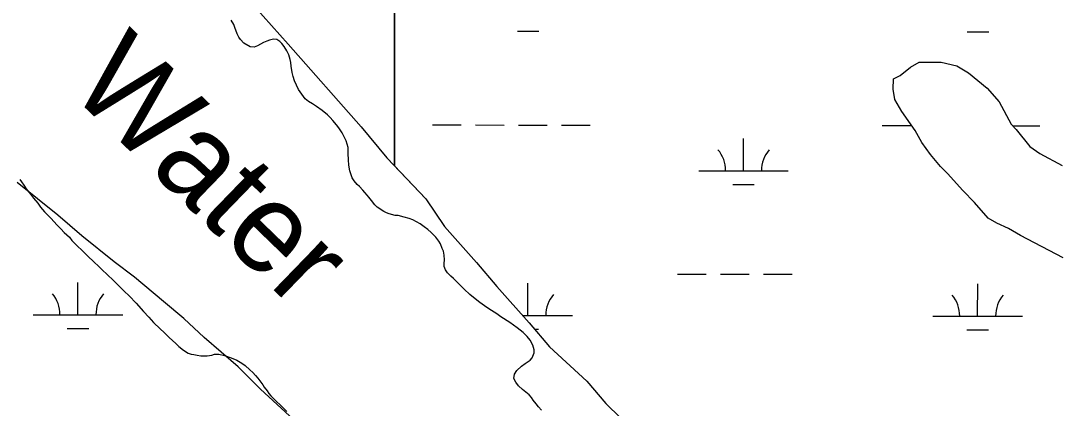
# Model space of a CAD drawing. Extents: x 3208593 to 3246461, y 812903 to 838290.
# Drawn here: x 3214585 to 3215741, y 820297 to 820730 of the extents above; entities that cross this region are included whole.
import ezdxf

# ---------------------------------------------------------------- set-up
doc = ezdxf.new("R2010")
doc.units = 0
for name, color, linetype in [('V-RIVR-IDEN', 7, 'Continuous'), ('V-SITE-VEGE', 7, 'Continuous'), ('V-TOPO-SHOR', 7, 'Continuous'), ('V-WETL-SWMP', 7, 'Continuous')]:
    doc.layers.add(name, color=color, linetype=linetype)

msp = doc.modelspace()

# ---------------------------------------------------------------- linework, layer by layer
at = {"layer": 'V-SITE-VEGE'}
for p, q in [((3214830.6, 820762.9), (3214883.7, 820703.4)), ((3214883.7, 820703.4), (3214965.1, 820611.3)), ((3215566.4, 820668.3), (3215577.9, 820677.8)), ((3215577.9, 820677.8), (3215587.5, 820683.4)), ((3215587.5, 820683.4), (3215612.3, 820683.3)), ((3215612.3, 820683.3), (3215629.5, 820679.4)), ((3215629.5, 820679.4), (3215642.8, 820671.6)), ((3215558.7, 820653.1), (3215558.8, 820664.6)), ((3215558.8, 820664.6), (3215566.4, 820668.3)), ((3215642.8, 820671.6), (3215663.6, 820654.3)), ((3215560.5, 820641.7), (3215558.7, 820653.1)), ((3215663.6, 820654.3), (3215676.9, 820639)), ((3215568.1, 820628.2), (3215560.5, 820641.7)), ((3215676.9, 820639), (3215690.1, 820614.1)), ((3215583.2, 820607.2), (3215568.1, 820628.2)), ((3214965.1, 820611.3), (3214993.5, 820576.7)), ((3215590.7, 820593.8), (3215583.2, 820607.2)), ((3215690.1, 820614.1), (3215695.8, 820608.3)), ((3215695.8, 820608.3), (3215710.9, 820589.1)), ((3215600.2, 820580.3), (3215590.7, 820593.8)), ((3215710.9, 820589.1), (3215722.3, 820581.4)), ((3214993.5, 820576.7), (3215037, 820530.7)), ((3215611.5, 820566.9), (3215600.2, 820580.3)), ((3215722.3, 820581.4), (3215747, 820567.9)), ((3215619.1, 820559.2), (3215611.5, 820566.9)), ((3214626.7, 820512.4), (3214581.2, 820549)), ((3215636.2, 820540), (3215619.1, 820559.2)), ((3215649.4, 820526.6), (3215636.2, 820540)), ((3215037, 820530.7), (3215057.8, 820500)), ((3215664.6, 820509.3), (3215649.4, 820526.6)), ((3214653.3, 820489.3), (3214626.7, 820512.4)), ((3215674.1, 820503.5), (3215664.6, 820509.3)), ((3215687.4, 820497.7), (3215674.1, 820503.5)), ((3215057.8, 820500), (3215093.8, 820459.7)), ((3215700.7, 820490), (3215687.4, 820497.7)), ((3214689.4, 820460.5), (3214653.3, 820489.3)), ((3215748.2, 820464.9), (3215700.7, 820490)), ((3214712.1, 820443.2), (3214689.4, 820460.5)), ((3215093.8, 820459.7), (3215116.5, 820432.8)), ((3214744.4, 820416.2), (3214712.1, 820443.2)), ((3215116.5, 820432.8), (3215152.5, 820392.5)), ((3214767.1, 820397), (3214744.4, 820416.2)), ((3214789.9, 820375.9), (3214767.1, 820397)), ((3215152.5, 820392.5), (3215175.2, 820365.7)), ((3214827.8, 820343.2), (3214789.9, 820375.9)), ((3215175.2, 820365.7), (3215216.9, 820327.2)), ((3214852.5, 820318.2), (3214827.8, 820343.2)), ((3214894.2, 820279.8), (3214852.5, 820318.2)), ((3215216.9, 820327.2), (3215237.8, 820302.3)), ((3215237.8, 820302.3), (3215277.6, 820263.9))]:
    msp.add_line(p, q, dxfattribs=at)
at = {"layer": 'V-TOPO-SHOR'}
for points in [[(3214937.6, 820613.5), (3214933.5, 820618.2), (3214930.3, 820621.5), (3214927.4, 820624.7), (3214921.6, 820629.4), (3214915.3, 820633.9), (3214910.6, 820636.7), (3214906.1, 820639.4), (3214902.5, 820642.4), (3214895, 820652.8), (3214890.7, 820662.5), (3214889.1, 820667.2), (3214887.9, 820671.9), (3214886.9, 820679), (3214886.5, 820683.1), (3214885.7, 820686.5), (3214884.2, 820691.4), (3214882, 820695.9), (3214879, 820700.9), (3214876.3, 820704.2), (3214874.1, 820706.6), (3214870.8, 820708.7), (3214867.2, 820709.1), (3214862.7, 820707.9), (3214859.7, 820706.9), (3214856, 820705.4), (3214852.5, 820703.6), (3214849.3, 820701.6), (3214845.4, 820700), (3214841, 820700.6), (3214833.9, 820704.4), (3214830.2, 820708.7), (3214828.6, 820711.3), (3214826.6, 820715), (3214823.9, 820722.1), (3214822.9, 820725.6), (3214820.1, 820730.1)], [(3215166.1, 820294.9), (3215162.9, 820298.4), (3215160.2, 820301.8), (3215156.8, 820306.1), (3215154.9, 820308.8), (3215152.5, 820311.8), (3215145, 820317.9), (3215140.7, 820321.8), (3215137.7, 820326), (3215135.5, 820330.3), (3215135.9, 820335), (3215138.7, 820339), (3215144, 820343.9), (3215147.9, 820346.8), (3215153.4, 820350.8), (3215155.6, 820353.4), (3215158, 820358.7), (3215158, 820362), (3215156.6, 820367.3), (3215153.4, 820373), (3215150.1, 820377), (3215145.7, 820381.5), (3215139, 820386.8), (3215130.8, 820392.7), (3215120.9, 820399), (3215116.2, 820402.3), (3215110.3, 820406.1), (3215105.2, 820409.6), (3215097.5, 820415.1), (3215092.1, 820419.3), (3215086.2, 820424), (3215079.9, 820429.9), (3215076.2, 820433.6), (3215072.8, 820436.8), (3215068.1, 820441.7), (3215065.1, 820444.4), (3215061.2, 820448.2), (3215059.2, 820451.5), (3215057.7, 820455.1), (3215057.7, 820458.6), (3215057.8, 820462.8), (3215057.5, 820467.7), (3215056.7, 820472.2), (3215055.5, 820475.3), (3215053.5, 820480.7), (3215051.5, 820483.6), (3215048.4, 820487.8), (3215043.2, 820493.3), (3215039.3, 820496.6), (3215035.4, 820499.6), (3215030.8, 820502.9), (3215022.6, 820507.2), (3215018.4, 820508.8), (3215012.9, 820510.4), (3215006.2, 820512.1), (3215003.1, 820512.3), (3214996.4, 820513.9), (3214993.4, 820515.3), (3214990.3, 820516.8), (3214983, 820521.4), (3214980.4, 820523.9), (3214976.5, 820529), (3214973.7, 820532.6), (3214971.5, 820534.9), (3214969.2, 820537.7), (3214966.8, 820540.3), (3214963.1, 820544.6), (3214960.5, 820546.7), (3214957, 820550.9), (3214955, 820554.4), (3214952.4, 820562.1), (3214951.4, 820568.4), (3214950.8, 820574.3), (3214950.6, 820581.4), (3214950.6, 820584.9), (3214950.4, 820588.1), (3214948.2, 820595.6), (3214943.9, 820604.4), (3214940.2, 820609.9), (3214937.6, 820613.5)], [(3214584, 820552.3), (3214585.8, 820549.6), (3214588.5, 820546), (3214591.3, 820542.1), (3214596.2, 820535.8), (3214599.4, 820531.5), (3214604.1, 820525.8), (3214607.1, 820521.6), (3214611.8, 820516.3), (3214615.1, 820513), (3214619.1, 820508.8), (3214625.4, 820501.8), (3214629.7, 820497.4), (3214633.7, 820493.3), (3214639.4, 820487.8), (3214642.3, 820484.4), (3214646.7, 820479.9), (3214655, 820471.7), (3214659.7, 820467.1), (3214667, 820460), (3214671.9, 820455.7), (3214675.1, 820452.4), (3214682.2, 820445.7), (3214687.7, 820440.4), (3214693.6, 820434.9), (3214700.7, 820427.6), (3214706.2, 820422.5), (3214713.9, 820414.2), (3214722.2, 820404.8), (3214727.9, 820398.7), (3214733.4, 820392.8), (3214740.7, 820385.5), (3214745, 820381.5), (3214750.7, 820375.8), (3214754.5, 820372.5), (3214758, 820369.2), (3214761.6, 820365.8), (3214766.7, 820361.7), (3214771.8, 820358.3), (3214775.2, 820357.5), (3214778.3, 820357), (3214782.1, 820356.2), (3214786.2, 820355.4), (3214789.5, 820355.4), (3214793.3, 820355.6), (3214798.2, 820356.4), (3214801.2, 820357.2), (3214806.1, 820357.2), (3214812.4, 820356), (3214820.1, 820353.3), (3214826.2, 820350.7), (3214831.9, 820347.2), (3214835.6, 820344.6), (3214840.8, 820339.9), (3214844.1, 820336.7), (3214847.1, 820333.6), (3214849.6, 820330.4), (3214853, 820326.1), (3214855.1, 820323), (3214856.9, 820320.4), (3214860.1, 820316.3), (3214862, 820313.3), (3214864, 820311), (3214866.6, 820308.4), (3214870.9, 820304.3), (3214874.3, 820301.1), (3214882.2, 820293.3)]]:
    msp.add_lwpolyline(points, dxfattribs=at)
at = {"layer": 'V-WETL-SWMP'}
for p, q in [((3215002, 821050.7), (3215002, 820567.7)), ((3215002, 820567.7), (3215002, 821050.7)), ((3214830.6, 820762.9), (3214883.7, 820703.4)), ((3215139.4, 820717.9), (3215163.4, 820717.8)), ((3215641.3, 820717.1), (3215665.3, 820717.1)), ((3214883.7, 820703.4), (3214965.1, 820611.3)), ((3215566.4, 820668.3), (3215577.9, 820677.8)), ((3215577.9, 820677.8), (3215587.5, 820683.4)), ((3215587.5, 820683.4), (3215612.3, 820683.3)), ((3215612.3, 820683.3), (3215629.5, 820679.4)), ((3215629.5, 820679.4), (3215642.8, 820671.6)), ((3215558.7, 820653.1), (3215558.8, 820664.6)), ((3215558.8, 820664.6), (3215566.4, 820668.3)), ((3215642.8, 820671.6), (3215663.6, 820654.3)), ((3215560.5, 820641.7), (3215558.7, 820653.1)), ((3215663.6, 820654.3), (3215676.9, 820639)), ((3215568.1, 820628.3), (3215560.5, 820641.7)), ((3215676.9, 820639), (3215690.1, 820614.1)), ((3215583.2, 820607.2), (3215568.1, 820628.3)), ((3214965.1, 820611.3), (3214993.5, 820576.7)), ((3215044.4, 820613.4), (3215076.4, 820613.3)), ((3215092.4, 820613.3), (3215124.4, 820613.2)), ((3215140.4, 820613.2), (3215172.4, 820613.2)), ((3215188.4, 820613.1), (3215220.4, 820613.1)), ((3215546.3, 820612.6), (3215578.3, 820612.6)), ((3215590.7, 820593.8), (3215583.2, 820607.2)), ((3215690.1, 820614.1), (3215695.8, 820608.3)), ((3215691.7, 820612.4), (3215722.3, 820612.4)), ((3215695.8, 820608.3), (3215710.9, 820589.1)), ((3215391.6, 820562.1), (3215391.7, 820598.1)), ((3215600.2, 820580.3), (3215590.7, 820593.8)), ((3215710.9, 820589.1), (3215722.3, 820581.4)), ((3214993.5, 820576.7), (3215002, 820567.7)), ((3215611.5, 820566.9), (3215600.2, 820580.3)), ((3215722.3, 820581.4), (3215747, 820567.9)), ((3215002, 820567.7), (3215037.1, 820530.7)), ((3215341.6, 820562.2), (3215441.6, 820562)), ((3215619.1, 820559.2), (3215611.5, 820566.9)), ((3214626.7, 820512.4), (3214581.2, 820549)), ((3215636.2, 820540), (3215619.1, 820559.2)), ((3215379.6, 820546.7), (3215403.6, 820546.7)), ((3215649.4, 820526.6), (3215636.2, 820540)), ((3215037.1, 820530.7), (3215057.8, 820500)), ((3215664.6, 820509.3), (3215649.4, 820526.6)), ((3214653.3, 820489.3), (3214626.7, 820512.4)), ((3215674.1, 820503.5), (3215664.6, 820509.3)), ((3215687.4, 820497.7), (3215674.1, 820503.5)), ((3215057.8, 820500), (3215093.8, 820459.7)), ((3215700.7, 820490), (3215687.4, 820497.7)), ((3214689.4, 820460.5), (3214653.3, 820489.3)), ((3215748.2, 820464.9), (3215700.7, 820490)), ((3214712.1, 820443.2), (3214689.4, 820460.5)), ((3215093.8, 820459.7), (3215116.5, 820432.8)), ((3215318, 820446.8), (3215350, 820446.7)), ((3215366, 820446.7), (3215398, 820446.7)), ((3215414, 820446.6), (3215446, 820446.6)), ((3214649, 820401.3), (3214649, 820437.3)), ((3214744.4, 820416.2), (3214712.1, 820443.2)), ((3215150.9, 820400.6), (3215151, 820436.6)), ((3215652.8, 820399.9), (3215652.9, 820435.9)), ((3215116.5, 820432.8), (3215152.5, 820392.5)), ((3214767.1, 820397), (3214744.4, 820416.2)), ((3214599, 820401.4), (3214699, 820401.3)), ((3215145.3, 820400.6), (3215200.9, 820400.5)), ((3215602.8, 820399.9), (3215702.8, 820399.8)), ((3214789.9, 820375.9), (3214767.1, 820397)), ((3215152.5, 820392.5), (3215175.2, 820365.7)), ((3214637, 820385.9), (3214661, 820385.9)), ((3214827.8, 820343.2), (3214789.9, 820375.9)), ((3215158.8, 820385.2), (3215162.9, 820385.2)), ((3215640.8, 820384.5), (3215664.8, 820384.4)), ((3215175.2, 820365.7), (3215216.9, 820327.2)), ((3214852.5, 820318.2), (3214827.8, 820343.2)), ((3214894.2, 820279.8), (3214852.5, 820318.2)), ((3215216.9, 820327.2), (3215237.8, 820302.3)), ((3215237.8, 820302.3), (3215277.6, 820263.9))]:
    msp.add_line(p, q, dxfattribs=at)
for centre, start, end in [((3215336.4, 820562.7), 359.1448, 40.6885), ((3215446.9, 820562.5), 139.1448, 180.6885), ((3214593.7, 820401.9), 359.1448, 40.6885), ((3214704.2, 820401.7), 139.1448, 180.6885), ((3215206.2, 820401), 139.1448, 180.6885), ((3215597.6, 820400.4), 359.1448, 40.6885), ((3215708.1, 820400.3), 139.1448, 180.6885)]:
    msp.add_arc(centre, 35.2, start, end, dxfattribs=at)

# ---------------------------------------------------------------- texts
at = {"layer": 'V-RIVR-IDEN'}
msp.add_text('Water', height=100, rotation=315.9316, dxfattribs=at).set_placement((3214636.4, 820652.3))

doc.saveas('drawing.dxf')
